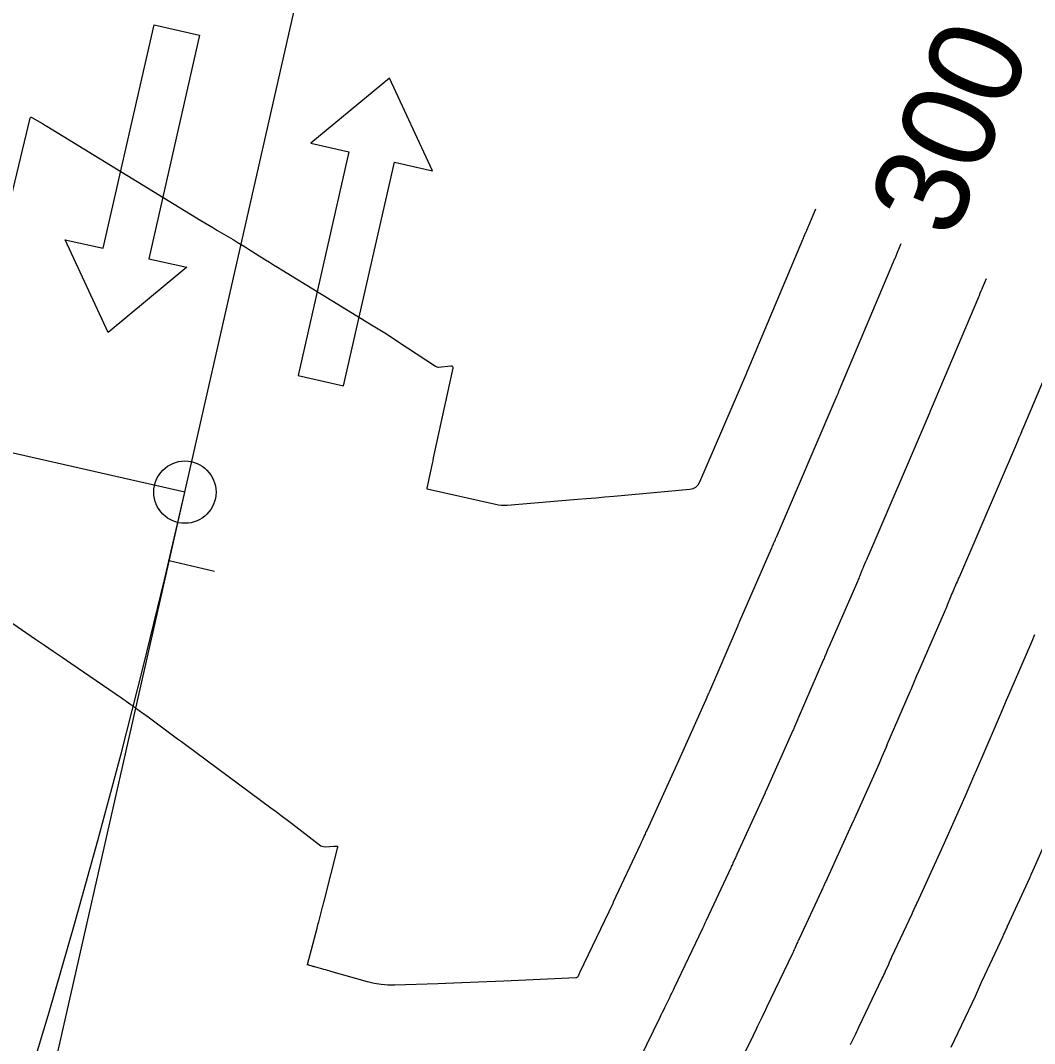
# Model space of a CAD drawing. Extents: x 1710723 to 1713003, y 548603 to 551142.
# Drawn here: x 1712236.2 to 1712301.3, y 549591.9 to 549657.6 of the extents above; entities that cross this region are included whole.
import ezdxf

# ---------------------------------------------------------------- set-up
doc = ezdxf.new("R2010")
doc.units = 0
for name, color, linetype in [('R_Contour Annot', 7, 'Continuous'), ('R_Contours', 7, 'Continuous'), ('R_Horz Alg', 7, 'Continuous'), ('R_Horz Alg Annot', 7, 'Continuous'), ('R_MOT', 7, 'Continuous')]:
    doc.layers.add(name, color=color, linetype=linetype)

msp = doc.modelspace()

# ---------------------------------------------------------------- linework, layer by layer
at = {"layer": 'R_Contours'}
for points in [[(1712235.629, 549646.197), (1712236.84, 549651.28), (1712236.856, 549651.321), (1712236.881, 549651.343), (1712236.914, 549651.346), (1712236.955, 549651.329), (1712237.635, 549650.934), (1712237.702, 549650.894), (1712237.77, 549650.854), (1712237.837, 549650.814), (1712237.904, 549650.773), (1712247.803, 549644.723), (1712248.06, 549644.567), (1712248.317, 549644.411), (1712248.575, 549644.256), (1712248.833, 549644.102), (1712249.867, 549643.486), (1712250.124, 549643.331), (1712250.382, 549643.175), (1712250.638, 549643.018), (1712250.893, 549642.859), (1712251.946, 549642.199), (1712252.207, 549642.037), (1712252.468, 549641.875), (1712252.729, 549641.713), (1712252.991, 549641.553), (1712258.756, 549638.029), (1712259.181, 549637.766), (1712259.605, 549637.5), (1712260.026, 549637.23), (1712260.445, 549636.956), (1712262.865, 549635.361), (1712262.909, 549635.337), (1712262.956, 549635.321), (1712263.005, 549635.313), (1712263.055, 549635.314), (1712263.841, 549635.385), (1712263.908, 549635.382), (1712263.951, 549635.357), (1712263.97, 549635.311), (1712263.965, 549635.244), (1712262.719, 549629.483), (1712262.679, 549629.3), (1712262.64, 549629.116), (1712262.3, 549627.543), (1712262.299, 549627.528), (1712262.303, 549627.516), (1712262.312, 549627.507), (1712262.327, 549627.502), (1712266.721, 549626.504), (1712266.905, 549626.469), (1712267.089, 549626.449), (1712267.275, 549626.443), (1712267.461, 549626.452), (1712271.976, 549626.826), (1712272.561, 549626.875), (1712273.145, 549626.925), (1712273.73, 549626.977), (1712274.314, 549627.03), (1712279.186, 549627.474), (1712279.396, 549627.518), (1712279.573, 549627.61), (1712279.714, 549627.749), (1712279.822, 549627.936), (1712282.832, 549634.94), (1712282.847, 549634.975), (1712282.861, 549635.009), (1712286.44, 549643.487), (1712286.463, 549643.542), (1712286.486, 549643.596), (1712286.509, 549643.651), (1712286.532, 549643.705), (1712286.639, 549643.962), (1712286.654, 549643.998), (1712286.669, 549644.033), (1712286.684, 549644.069), (1712286.699, 549644.104), (1712286.759, 549644.247), (1712286.774, 549644.282), (1712286.789, 549644.318), (1712286.804, 549644.354), (1712286.819, 549644.389), (1712287.263, 549645.462)], [(1712292.734, 549643.215), (1712292.714, 549643.165), (1712292.672, 549643.064), (1712292.629, 549642.962), (1712292.587, 549642.861), (1712292.544, 549642.76), (1712292.331, 549642.254), (1712292.309, 549642.203), (1712292.288, 549642.152), (1712292.266, 549642.101), (1712292.245, 549642.049), (1712292.159, 549641.844), (1712292.138, 549641.793), (1712292.116, 549641.742), (1712292.095, 549641.69), (1712292.073, 549641.639), (1712288.772, 549633.821), (1712288.735, 549633.733), (1712288.698, 549633.646), (1712288.661, 549633.559), (1712288.624, 549633.472), (1712284.715, 549624.376), (1712284.699, 549624.34), (1712284.683, 549624.303), (1712284.668, 549624.267), (1712284.652, 549624.23), (1712284.588, 549624.084), (1712284.572, 549624.047), (1712284.557, 549624.01), (1712284.541, 549623.974), (1712284.526, 549623.937), (1712284.466, 549623.786), (1712284.451, 549623.749), (1712284.435, 549623.712), (1712284.42, 549623.675), (1712284.404, 549623.637), (1712282.353, 549618.936), (1712282.349, 549618.927), (1712282.272, 549618.74), (1712282.259, 549618.709), (1712282.246, 549618.678), (1712282.233, 549618.647), (1712282.219, 549618.615), (1712280.44, 549614.501), (1712280.423, 549614.461), (1712280.393, 549614.395), (1712280.382, 549614.368), (1712280.37, 549614.341), (1712280.317, 549614.217), (1712280.306, 549614.191), (1712280.295, 549614.166), (1712280.284, 549614.141), (1712280.273, 549614.116), (1712278.367, 549609.842), (1712278.354, 549609.813), (1712278.353, 549609.81), (1712276.418, 549605.574), (1712276.383, 549605.498), (1712276.348, 549605.422), (1712276.313, 549605.345), (1712276.277, 549605.269), (1712276.136, 549604.963), (1712276.101, 549604.887), (1712276.065, 549604.811), (1712276.03, 549604.734), (1712275.994, 549604.658), (1712274.267, 549600.965), (1712274.259, 549600.947), (1712274.243, 549600.912), (1712274.238, 549600.901), (1712274.235, 549600.895), (1712272.126, 549596.478), (1712272.109, 549596.442), (1712272.091, 549596.406), (1712272.074, 549596.371), (1712272.057, 549596.335), (1712271.988, 549596.192), (1712271.967, 549596.16), (1712271.942, 549596.137), (1712271.91, 549596.123), (1712271.874, 549596.117), (1712269.128, 549595.996), (1712268.657, 549595.976), (1712268.186, 549595.955), (1712267.715, 549595.935), (1712267.244, 549595.914), (1712265.075, 549595.82), (1712264.557, 549595.798), (1712264.038, 549595.778), (1712263.52, 549595.759), (1712263.001, 549595.742), (1712260.253, 549595.655), (1712259.809, 549595.658), (1712259.37, 549595.695), (1712258.934, 549595.765), (1712258.503, 549595.87), (1712256.151, 549596.534), (1712256.039, 549596.565), (1712255.927, 549596.597), (1712255.815, 549596.628), (1712255.703, 549596.659), (1712255.109, 549596.823), (1712255.069, 549596.834), (1712255.029, 549596.845), (1712254.99, 549596.856), (1712254.95, 549596.867), (1712254.732, 549596.929), (1712254.701, 549596.938), (1712254.649, 549596.952), (1712254.64, 549596.956), (1712254.635, 549596.962), (1712254.633, 549596.969), (1712254.634, 549596.979), (1712255.26, 549599.315), (1712255.285, 549599.411), (1712255.311, 549599.508), (1712255.337, 549599.605), (1712255.362, 549599.702), (1712255.635, 549600.736), (1712255.655, 549600.812), (1712255.674, 549600.888), (1712255.694, 549600.963), (1712255.713, 549601.039), (1712256.602, 549604.493), (1712256.604, 549604.517), (1712256.598, 549604.534), (1712256.583, 549604.544), (1712256.559, 549604.547), (1712256.444, 549604.542), (1712256.415, 549604.541), (1712256.386, 549604.54), (1712256.358, 549604.539), (1712256.329, 549604.538), (1712255.773, 549604.512), (1712255.673, 549604.516), (1712255.579, 549604.537), (1712255.49, 549604.574), (1712255.406, 549604.628), (1712253.609, 549606.018), (1712253.282, 549606.27), (1712252.954, 549606.519), (1712252.624, 549606.767), (1712252.292, 549607.013), (1712246.805, 549611.066), (1712246.553, 549611.253), (1712246.301, 549611.44), (1712246.049, 549611.627), (1712245.798, 549611.815), (1712244.496, 549612.788), (1712244.394, 549612.864), (1712244.291, 549612.94), (1712244.187, 549613.015), (1712244.084, 549613.09), (1712243.61, 549613.428), (1712243.535, 549613.482), (1712243.46, 549613.536), (1712243.385, 549613.59), (1712243.309, 549613.643), (1712243.008, 549613.857), (1712242.933, 549613.911), (1712242.857, 549613.964), (1712242.781, 549614.016), (1712242.705, 549614.069), (1712239.457, 549616.284), (1712238.89, 549616.671), (1712238.324, 549617.058), (1712237.758, 549617.445), (1712237.192, 549617.833), (1712232.116, 549621.311)], [(1712298.201, 549640.969), (1712297.947, 549640.367), (1712297.927, 549640.319), (1712297.906, 549640.271), (1712297.886, 549640.223), (1712297.866, 549640.175), (1712297.786, 549639.983), (1712297.766, 549639.935), (1712297.746, 549639.887), (1712297.726, 549639.839), (1712297.705, 549639.791), (1712294.683, 549632.632), (1712294.617, 549632.475), (1712294.55, 549632.317), (1712294.483, 549632.16), (1712294.415, 549632.003), (1712290.6, 549623.126), (1712290.568, 549623.05), (1712290.535, 549622.974), (1712290.502, 549622.899), (1712290.469, 549622.823), (1712290.338, 549622.521), (1712290.305, 549622.446), (1712290.273, 549622.37), (1712290.241, 549622.294), (1712290.21, 549622.217), (1712290.086, 549621.906), (1712290.054, 549621.829), (1712290.022, 549621.752), (1712289.99, 549621.676), (1712289.957, 549621.599), (1712288.076, 549617.286), (1712288.067, 549617.265), (1712287.889, 549616.834), (1712287.859, 549616.762), (1712287.828, 549616.69), (1712287.797, 549616.618), (1712287.767, 549616.546), (1712286.139, 549612.782), (1712286.122, 549612.744), (1712286.095, 549612.682), (1712286.084, 549612.657), (1712286.073, 549612.632), (1712285.915, 549612.259), (1712285.886, 549612.193), (1712285.858, 549612.127), (1712285.829, 549612.061), (1712285.8, 549611.995), (1712284.058, 549608.091), (1712284.047, 549608.066), (1712284.026, 549608.016), (1712284.018, 549607.999), (1712284.014, 549607.991), (1712282.209, 549604.038), (1712282.176, 549603.966), (1712282.143, 549603.895), (1712282.11, 549603.823), (1712282.077, 549603.752), (1712281.945, 549603.466), (1712281.912, 549603.395), (1712281.878, 549603.323), (1712281.845, 549603.252), (1712281.812, 549603.18), (1712280.229, 549599.796), (1712280.21, 549599.754), (1712280.19, 549599.712), (1712280.172, 549599.67), (1712280.153, 549599.628), (1712280.08, 549599.46), (1712280.061, 549599.418), (1712280.042, 549599.376), (1712280.023, 549599.334), (1712280.003, 549599.292), (1712278.183, 549595.481), (1712278.106, 549595.321), (1712278.029, 549595.161), (1712277.952, 549595.001), (1712277.875, 549594.841), (1712277.566, 549594.202), (1712277.488, 549594.042), (1712277.411, 549593.883), (1712277.333, 549593.723), (1712277.255, 549593.563), (1712275.974, 549590.947)], [(1712303.338, 549637.943), (1712300.594, 549631.444), (1712300.498, 549631.216), (1712300.401, 549630.989), (1712300.304, 549630.762), (1712300.207, 549630.535), (1712296.485, 549621.875), (1712296.436, 549621.76), (1712296.387, 549621.646), (1712296.337, 549621.531), (1712296.287, 549621.417), (1712296.087, 549620.959), (1712296.038, 549620.844), (1712295.989, 549620.729), (1712295.942, 549620.614), (1712295.895, 549620.498), (1712295.705, 549620.027), (1712295.658, 549619.91), (1712295.61, 549619.793), (1712295.56, 549619.677), (1712295.51, 549619.561), (1712293.799, 549615.636), (1712293.794, 549615.625), (1712293.785, 549615.603), (1712293.505, 549614.928), (1712293.458, 549614.815), (1712293.41, 549614.702), (1712293.362, 549614.589), (1712293.314, 549614.476), (1712291.837, 549611.062), (1712291.822, 549611.027), (1712291.796, 549610.969), (1712291.786, 549610.946), (1712291.776, 549610.922), (1712291.512, 549610.301), (1712291.466, 549610.194), (1712291.42, 549610.087), (1712291.373, 549609.98), (1712291.326, 549609.873), (1712289.749, 549606.34), (1712289.737, 549606.312), (1712289.725, 549606.284), (1712289.701, 549606.228), (1712289.695, 549606.214), (1712289.689, 549606.2), (1712289.682, 549606.186), (1712289.676, 549606.172), (1712287.999, 549602.502), (1712287.969, 549602.435), (1712287.938, 549602.368), (1712287.907, 549602.302), (1712287.877, 549602.235), (1712287.754, 549601.969), (1712287.723, 549601.902), (1712287.692, 549601.836), (1712287.661, 549601.769), (1712287.63, 549601.703), (1712286.191, 549598.627), (1712286.155, 549598.549), (1712286.12, 549598.472), (1712286.085, 549598.393), (1712286.05, 549598.315), (1712285.913, 549598.001), (1712285.879, 549597.923), (1712285.843, 549597.845), (1712285.807, 549597.767), (1712285.771, 549597.69), (1712284.11, 549594.213), (1712284.039, 549594.064), (1712283.967, 549593.915), (1712283.896, 549593.766), (1712283.824, 549593.617), (1712283.535, 549593.021), (1712283.463, 549592.872), (1712283.391, 549592.723), (1712283.318, 549592.574), (1712283.245, 549592.425), (1712282.095, 549590.075)], [(1712289.505, 549591.84), (1712289.772, 549592.392), (1712289.839, 549592.53), (1712289.906, 549592.669), (1712289.972, 549592.807), (1712290.038, 549592.945), (1712291.539, 549596.087), (1712291.592, 549596.201), (1712291.645, 549596.314), (1712291.696, 549596.428), (1712291.747, 549596.543), (1712291.947, 549597.002), (1712291.998, 549597.117), (1712292.049, 549597.231), (1712292.101, 549597.345), (1712292.154, 549597.458), (1712293.448, 549600.225), (1712293.476, 549600.286), (1712293.505, 549600.348), (1712293.534, 549600.41), (1712293.562, 549600.471), (1712293.676, 549600.718), (1712293.705, 549600.78), (1712293.733, 549600.842), (1712293.762, 549600.903), (1712293.79, 549600.965), (1712295.338, 549604.353), (1712295.346, 549604.372), (1712295.355, 549604.392), (1712295.364, 549604.411), (1712295.372, 549604.431), (1712295.406, 549604.51), (1712295.415, 549604.53), (1712295.423, 549604.549), (1712295.432, 549604.569), (1712295.441, 549604.589), (1712296.852, 549607.752), (1712296.917, 549607.9), (1712296.982, 549608.047), (1712297.046, 549608.195), (1712297.11, 549608.344), (1712297.479, 549609.213), (1712297.489, 549609.234), (1712297.498, 549609.256), (1712297.522, 549609.31), (1712297.536, 549609.342), (1712298.861, 549612.407), (1712298.927, 549612.56), (1712298.993, 549612.714), (1712299.058, 549612.868), (1712299.122, 549613.022), (1712299.503, 549613.941), (1712299.517, 549613.975), (1712299.521, 549613.986), (1712301.064, 549617.522), (1712301.131, 549617.678), (1712301.197, 549617.834), (1712301.261, 549617.99), (1712301.325, 549618.147)], [(1712295.966, 549591.678), (1712297.307, 549594.485), (1712297.377, 549594.634), (1712297.446, 549594.784), (1712297.514, 549594.934), (1712297.581, 549595.085), (1712297.844, 549595.689), (1712297.911, 549595.84), (1712297.978, 549595.99), (1712298.047, 549596.14), (1712298.116, 549596.289), (1712299.265, 549598.747), (1712299.292, 549598.804), (1712299.318, 549598.86), (1712299.345, 549598.917), (1712299.371, 549598.974), (1712299.476, 549599.201), (1712299.502, 549599.258), (1712299.529, 549599.315), (1712299.555, 549599.372), (1712299.581, 549599.429), (1712300.999, 549602.533), (1712301.01, 549602.559), (1712301.022, 549602.584), (1712301.033, 549602.609), (1712301.044, 549602.635), (1712301.088, 549602.736), (1712301.099, 549602.762), (1712301.11, 549602.787), (1712301.121, 549602.812), (1712301.132, 549602.837), (1712302.378, 549605.631)]]:
    msp.add_lwpolyline(points, dxfattribs=at)
at = {"layer": 'R_Horz Alg'}
msp.add_line((1712246.774, 549627.283), (1712450.808, 550525.825), dxfattribs=at)
msp.add_arc((1711727.021, 549745.305), 532.984, 270.64281, 347.20664, dxfattribs=at)
at = {"layer": 'R_Horz Alg Annot'}
msp.add_line((1712153.627, 549217.073), (1712246.774, 549627.283), dxfattribs=at)
for points in [[(1712246.774, 549627.283), (1712129.753, 549653.855)], [(1712248.676, 549622.197), (1712245.756, 549622.886)]]:
    msp.add_lwpolyline(points, dxfattribs=at)
msp.add_circle((1712246.774, 549627.283), 2, dxfattribs=at)
at = {"layer": 'R_MOT'}
for points in [[(1712246.898, 549641.713), (1712241.848, 549637.535), (1712239.097, 549643.484), (1712241.535, 549642.931), (1712244.793, 549657.277), (1712247.718, 549656.613), (1712244.46, 549642.266)], [(1712262.659, 549647.896), (1712259.908, 549653.845), (1712254.858, 549649.668), (1712257.295, 549649.114), (1712254.038, 549634.767), (1712256.963, 549634.103), (1712260.221, 549648.45)]]:
    msp.add_lwpolyline(points, close=True, dxfattribs=at)

# ---------------------------------------------------------------- texts
at = {"layer": 'R_Contour Annot'}
msp.add_text('300', height=6, rotation=67.66869, dxfattribs=at).set_placement((1712296.048, 549643.386))

doc.saveas('drawing.dxf')
